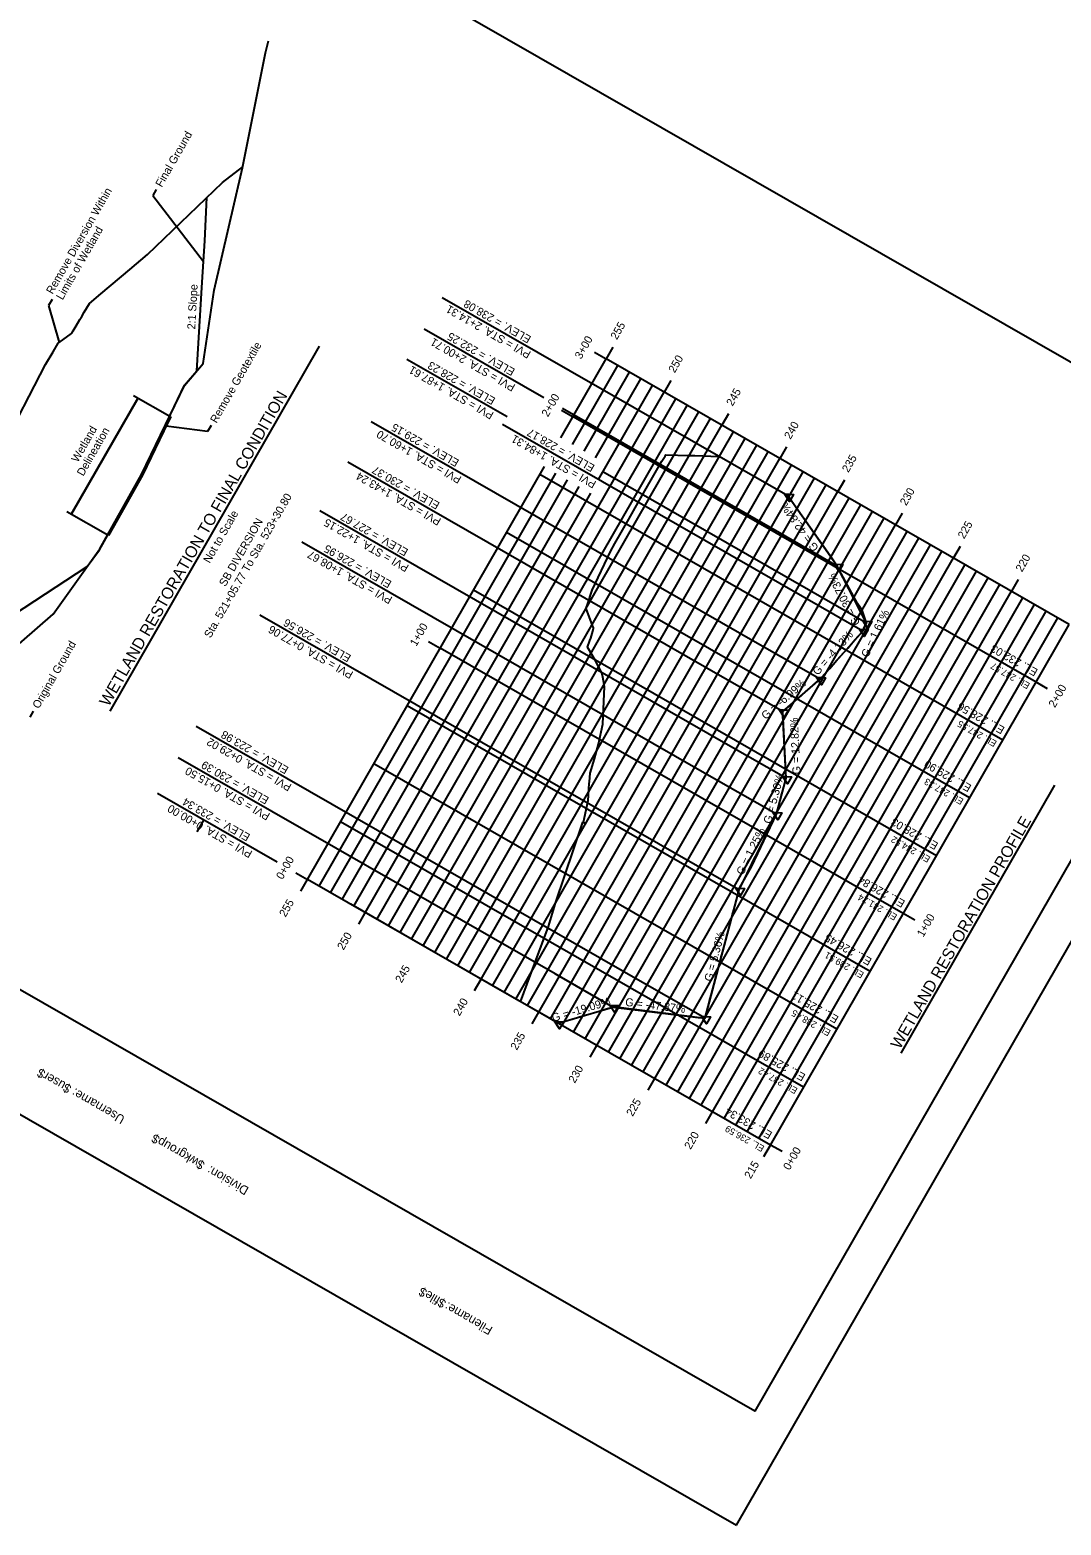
# Model space of a CAD drawing. Extents: x 1160918 to 1162032, y 616868 to 618272.
# Drawn here: x 1161130 to 1161516, y 616868 to 617428 of the extents above; entities that cross this region are included whole.
import ezdxf

# ---------------------------------------------------------------- set-up
doc = ezdxf.new("R2010")
doc.units = 0
for name, color, linetype in [('ANNOTATION', 7, 'Continuous'), ('BORDER', 7, 'Continuous'), ('D_Roadway_Centerline', 7, 'Continuous'), ('D_Roadway_Centerline_CurveData', 7, 'Continuous'), ('D_Roadway_Centerline_Text', 7, 'Continuous'), ('DIMENSIONS', 7, 'Continuous'), ('H_V ANNOTATION', 7, 'Continuous'), ('MAJOR', 7, 'Continuous'), ('MINOR', 7, 'Continuous'), ('PLOT BOUNDARY', 7, 'Continuous'), ('Plot Boundary_1', 7, 'Continuous'), ('S_Roadway_Centerline', 7, 'Continuous')]:
    doc.layers.add(name, color=color, linetype=linetype)

msp = doc.modelspace()

# ---------------------------------------------------------------- linework, layer by layer
at = {"layer": 'ANNOTATION'}
for p, q in [((1161177.15, 617368.59), (1161175.89, 617366.39)), ((1161175.89, 617366.39), (1161194.97, 617341.61)), ((1161138.17, 617327.38), (1161136.91, 617325.18)), ((1161136.91, 617325.18), (1161140.79, 617311.27)), ((1161170.41, 617290.47), (1161145.47, 617246.98)), ((1161145.47, 617246.98), (1161170.41, 617290.47)), ((1161168.69, 617291.45), (1161182.26, 617283.67)), ((1161196.47, 617277.89), (1161180.96, 617279.87)), ((1161197.74, 617280.09), (1161196.47, 617277.89)), ((1161143.75, 617247.97), (1161159.04, 617239.2)), ((1161131.15, 617173.06), (1161129.89, 617170.86))]:
    msp.add_line(p, q, dxfattribs=at)
msp.add_lwpolyline([(1161159.5, 617238.96), (1161164.37, 617247.58), (1161172.16, 617261.48), (1161180.18, 617278.18), (1161182.76, 617283.58)], dxfattribs=at)
at = {"layer": 'BORDER'}
msp.add_lwpolyline([(1160946.07, 617171.9), (1161344.12, 617865.84), (1161799.52, 617604.62), (1161401.47, 616910.68)], close=True, dxfattribs=at)
at = {"layer": 'D_Roadway_Centerline'}
for p, q in [((1161432.4, 617227.46), (1161413.89, 617253.76)), ((1161443.34, 617206.09), (1161432.4, 617227.46)), ((1161441.93, 617203.08), (1161443.34, 617206.09)), ((1161425.95, 617185.03), (1161441.93, 617203.08)), ((1161411.97, 617172.93), (1161425.95, 617185.03)), ((1161413.2, 617147.91), (1161411.97, 617172.93)), ((1161409.59, 617134.44), (1161413.2, 617147.91)), ((1161395.57, 617106.04), (1161409.59, 617134.44)), ((1161382.83, 617057.96), (1161395.57, 617106.04)), ((1161327.79, 617056.08), (1161348.34, 617062.16)), ((1161348.34, 617062.16), (1161382.83, 617057.96))]:
    msp.add_line(p, q, dxfattribs=at)
for points in [[(1161084.35, 617183.4), (1161151.39, 617227.32), (1161155.9, 617233.6), (1161172.14, 617262.58), (1161187.84, 617295.32), (1161192.39, 617300.62), (1161194.47, 617333.83), (1161195.48, 617349.39), (1161196.23, 617365.67), (1161196.56, 617365.98)], [(1161327.79, 617056.08), (1161330.44, 617056.87), (1161333.09, 617057.65), (1161335.75, 617058.44), (1161338.4, 617059.22), (1161341.05, 617060.01), (1161343.7, 617060.79), (1161346.35, 617061.57), (1161348.34, 617062.16), (1161349.61, 617062.01), (1161354.72, 617061.39), (1161359.82, 617060.76), (1161364.93, 617060.14), (1161370.03, 617059.52), (1161375.13, 617058.9), (1161380.24, 617058.28), (1161382.83, 617057.96), (1161383.02, 617058.65), (1161383.02, 617058.65), (1161383.09, 617058.94), (1161383.63, 617060.94), (1161384.16, 617062.95), (1161384.69, 617064.95), (1161385.22, 617066.95), (1161385.75, 617068.95), (1161386.28, 617070.95), (1161386.81, 617072.95), (1161387.34, 617074.96), (1161387.87, 617076.96), (1161388.4, 617078.96), (1161388.93, 617080.96), (1161389.46, 617082.96), (1161389.99, 617084.96), (1161390.52, 617086.96), (1161391.05, 617088.97), (1161391.58, 617090.97), (1161392.11, 617092.97), (1161392.64, 617094.97), (1161393.17, 617096.97), (1161393.7, 617098.97), (1161394.23, 617100.97), (1161394.76, 617102.98), (1161395.29, 617104.98), (1161395.57, 617106.04), (1161395.99, 617106.88), (1161396.03, 617106.95), (1161396.03, 617106.95), (1161396.88, 617108.68), (1161397.76, 617110.48), (1161398.65, 617112.27), (1161399.54, 617114.07), (1161400.43, 617115.87), (1161401.31, 617117.66), (1161402.2, 617119.46), (1161403.09, 617121.26), (1161403.97, 617123.05), (1161404.86, 617124.85), (1161405.75, 617126.65), (1161406.63, 617128.44), (1161407.52, 617130.24), (1161408.41, 617132.04), (1161409.3, 617133.84), (1161409.59, 617134.44), (1161409.95, 617135.77), (1161410.48, 617137.76), (1161411.02, 617139.76), (1161411.55, 617141.76), (1161412.09, 617143.76), (1161412.63, 617145.76), (1161413.16, 617147.76), (1161413.2, 617147.91), (1161413.09, 617150.1), (1161412.98, 617152.47), (1161412.86, 617154.85), (1161412.74, 617157.22), (1161412.63, 617159.59), (1161412.51, 617161.96), (1161412.39, 617164.34), (1161412.28, 617166.71), (1161412.16, 617169.08), (1161412.04, 617171.46), (1161411.97, 617172.93), (1161412.58, 617173.45), (1161414.18, 617174.84), (1161415.78, 617176.23), (1161417.39, 617177.61), (1161418.99, 617179), (1161420.59, 617180.39), (1161422.19, 617181.77), (1161423.79, 617183.16), (1161425.39, 617184.55), (1161425.95, 617185.03), (1161426.83, 617186.03), (1161427.63, 617186.93), (1161428.19, 617187.56), (1161429.54, 617189.09), (1161430.89, 617190.62), (1161432.25, 617192.15), (1161433.6, 617193.68), (1161434.95, 617195.2), (1161436.31, 617196.73), (1161437.66, 617198.26), (1161439.01, 617199.79), (1161440.37, 617201.32), (1161441.72, 617202.85), (1161441.93, 617203.08), (1161442.65, 617204.62), (1161443.34, 617206.09), (1161443.02, 617206.72), (1161441.35, 617209.98), (1161439.68, 617213.25), (1161438.01, 617216.51), (1161436.33, 617219.77), (1161434.66, 617223.04), (1161432.99, 617226.3), (1161432.4, 617227.46), (1161430.64, 617229.96), (1161430.53, 617230.11), (1161430.53, 617230.11), (1161427.92, 617233.82), (1161425.2, 617237.69), (1161422.48, 617241.55), (1161419.76, 617245.42), (1161417.04, 617249.29), (1161414.32, 617253.15), (1161413.89, 617253.76)]]:
    msp.add_lwpolyline(points, dxfattribs=at)
at = {"layer": 'D_Roadway_Centerline_CurveData'}
for p, q in [((1161392.21, 617266.2), (1161284.37, 617328.05)), ((1161322.44, 617290.54), (1161277.6, 617316.25)), ((1161308.65, 617283.35), (1161271.09, 617304.89)), ((1161410.72, 617239.9), (1161329.4, 617286.54)), ((1161404.27, 617197.47), (1161257.69, 617281.54)), ((1161420.24, 617215.52), (1161307, 617280.48)), ((1161390.29, 617185.37), (1161249.01, 617266.4)), ((1161413.89, 617253.76), (1161392.21, 617266.2)), ((1161421.66, 617218.52), (1161344.57, 617262.74)), ((1161391.52, 617160.35), (1161238.52, 617248.11)), ((1161432.4, 617227.46), (1161410.72, 617239.9)), ((1161387.91, 617146.88), (1161231.81, 617236.42)), ((1161441.93, 617203.08), (1161420.24, 617215.52)), ((1161443.34, 617206.09), (1161421.66, 617218.52)), ((1161373.89, 617118.48), (1161216.08, 617209)), ((1161425.95, 617185.03), (1161404.27, 617197.47)), ((1161411.97, 617172.93), (1161390.29, 617185.37)), ((1161361.15, 617070.4), (1161192.17, 617167.32)), ((1161413.2, 617147.91), (1161391.52, 617160.35)), ((1161326.66, 617074.6), (1161185.45, 617155.6)), ((1161409.59, 617134.44), (1161387.91, 617146.88)), ((1161222.57, 617116.43), (1161177.74, 617142.15)), ((1161395.57, 617106.04), (1161373.89, 617118.48)), ((1161306.11, 617068.52), (1161250.07, 617100.66)), ((1161348.34, 617062.16), (1161326.66, 617074.6)), ((1161382.83, 617057.96), (1161361.15, 617070.4)), ((1161327.79, 617056.08), (1161306.11, 617068.52))]:
    msp.add_line(p, q, dxfattribs=at)
for points in [[(1161412.59, 617254.51), (1161415.94, 617254.32), (1161414.45, 617251.71)], [(1161431.1, 617228.2), (1161434.45, 617228.01), (1161432.96, 617225.41)], [(1161442.04, 617206.83), (1161445.39, 617206.64), (1161443.9, 617204.04)], [(1161440.63, 617203.83), (1161443.97, 617203.64), (1161442.48, 617201.04)], [(1161424.65, 617185.78), (1161428, 617185.59), (1161426.51, 617182.98)], [(1161410.67, 617173.67), (1161414.02, 617173.48), (1161412.53, 617170.88)], [(1161411.9, 617148.66), (1161415.25, 617148.47), (1161413.76, 617145.86)], [(1161408.29, 617135.18), (1161411.64, 617134.99), (1161410.15, 617132.39)], [(1161394.27, 617106.78), (1161397.62, 617106.59), (1161396.13, 617103.99)], [(1161347.04, 617062.91), (1161350.39, 617062.72), (1161348.9, 617060.12)], [(1161381.53, 617058.71), (1161384.88, 617058.51), (1161383.39, 617055.91)], [(1161326.49, 617056.83), (1161329.84, 617056.64), (1161328.35, 617054.03)]]:
    msp.add_lwpolyline(points, close=True, dxfattribs=at)
at = {"layer": 'H_V ANNOTATION'}
for p, q in [((1161159.9, 617173.02), (1161238.38, 617309.83)), ((1161456.37, 617044.87), (1161513.96, 617145.27))]:
    msp.add_line(p, q, dxfattribs=at)
at = {"layer": 'MAJOR'}
for p, q in [((1161341.48, 617307.61), (1161345.82, 617305.13)), ((1161348.31, 617309.46), (1161345.82, 617305.13)), ((1161348.31, 617309.46), (1161345.82, 617305.13)), ((1161328.84, 617275.53), (1161345.82, 617305.13)), ((1161519.31, 617205.61), (1161345.82, 617305.13)), ((1161369.99, 617297.02), (1161367.51, 617292.69)), ((1161255.56, 617097.52), (1161367.51, 617292.69)), ((1161329.05, 617285.93), (1161333.38, 617283.44)), ((1161506.87, 617183.93), (1161333.38, 617283.44)), ((1161391.68, 617284.58), (1161389.19, 617280.25)), ((1161277.24, 617085.08), (1161389.19, 617280.25)), ((1161413.36, 617272.14), (1161410.88, 617267.81)), ((1161298.93, 617072.64), (1161410.88, 617267.81)), ((1161233.87, 617109.95), (1161322.67, 617264.76)), ((1161320.61, 617060.2), (1161432.56, 617255.37)), ((1161435.05, 617259.71), (1161432.56, 617255.37)), ((1161456.74, 617247.27), (1161454.25, 617242.93)), ((1161342.3, 617047.76), (1161454.25, 617242.93)), ((1161478.42, 617234.83), (1161475.93, 617230.49)), ((1161363.98, 617035.32), (1161475.93, 617230.49)), ((1161500.11, 617222.39), (1161497.62, 617218.05)), ((1161385.67, 617022.88), (1161497.62, 617218.05)), ((1161407.36, 617010.44), (1161519.31, 617205.61)), ((1161279.29, 617199.18), (1161283.63, 617196.7)), ((1161457.11, 617097.19), (1161283.63, 617196.7)), ((1161511.2, 617181.44), (1161506.87, 617183.93)), ((1161192.55, 617127.89), (1161195.03, 617132.23)), ((1161229.53, 617112.44), (1161233.87, 617109.95)), ((1161231.38, 617105.62), (1161233.87, 617109.95)), ((1161231.38, 617105.62), (1161233.87, 617109.95)), ((1161407.36, 617010.44), (1161233.87, 617109.95)), ((1161253.07, 617093.18), (1161255.56, 617097.52)), ((1161461.45, 617094.7), (1161457.11, 617097.19)), ((1161296.44, 617068.3), (1161298.93, 617072.64)), ((1161318.12, 617055.86), (1161320.61, 617060.2)), ((1161339.81, 617043.42), (1161342.3, 617047.76)), ((1161361.5, 617030.98), (1161363.98, 617035.32)), ((1161383.18, 617018.54), (1161385.67, 617022.88)), ((1161404.87, 617006.11), (1161407.36, 617010.44)), ((1161411.69, 617007.96), (1161407.36, 617010.44))]:
    msp.add_line(p, q, dxfattribs=at)
at = {"layer": 'MINOR'}
for p, q in [((1161333.18, 617273.04), (1161350.16, 617302.64)), ((1161337.52, 617270.55), (1161354.49, 617300.15)), ((1161519.31, 617205.61), (1161345.82, 617305.13)), ((1161341.85, 617268.06), (1161358.83, 617297.66)), ((1161342.92, 617259.88), (1161363.17, 617295.18)), ((1161259.89, 617095.03), (1161371.84, 617290.2)), ((1161264.23, 617092.54), (1161376.18, 617287.71)), ((1161268.57, 617090.05), (1161380.52, 617285.22)), ((1161272.9, 617087.56), (1161384.85, 617282.74)), ((1161281.58, 617082.59), (1161393.53, 617277.76)), ((1161285.92, 617080.1), (1161397.87, 617275.27)), ((1161290.25, 617077.61), (1161402.2, 617272.78)), ((1161294.59, 617075.13), (1161406.54, 617270.3)), ((1161238.21, 617107.47), (1161327, 617262.27)), ((1161303.26, 617070.15), (1161415.21, 617265.32)), ((1161307.6, 617067.66), (1161419.55, 617262.83)), ((1161311.94, 617065.17), (1161423.89, 617260.35)), ((1161494.43, 617162.24), (1161320.94, 617261.75)), ((1161242.54, 617104.98), (1161331.34, 617259.78)), ((1161246.88, 617102.49), (1161335.68, 617257.29)), ((1161251.22, 617100), (1161340.01, 617254.81)), ((1161316.28, 617062.69), (1161428.23, 617257.86)), ((1161324.95, 617057.71), (1161436.9, 617252.88)), ((1161329.29, 617055.22), (1161441.24, 617250.39)), ((1161333.62, 617052.74), (1161445.57, 617247.91)), ((1161337.96, 617050.25), (1161449.91, 617245.42)), ((1161481.99, 617140.56), (1161308.5, 617240.07)), ((1161346.64, 617045.27), (1161458.59, 617240.44)), ((1161350.97, 617042.78), (1161462.92, 617237.96)), ((1161355.31, 617040.3), (1161467.26, 617235.47)), ((1161359.65, 617037.81), (1161471.6, 617232.98)), ((1161368.32, 617032.83), (1161480.27, 617228)), ((1161372.66, 617030.34), (1161484.61, 617225.52)), ((1161377, 617027.86), (1161488.95, 617223.03)), ((1161469.55, 617118.87), (1161296.06, 617218.38)), ((1161381.33, 617025.37), (1161493.28, 617220.54)), ((1161390.01, 617020.39), (1161501.96, 617215.57)), ((1161394.34, 617017.91), (1161506.29, 617213.08)), ((1161398.68, 617015.42), (1161510.63, 617210.59)), ((1161403.02, 617012.93), (1161514.97, 617208.1)), ((1161444.67, 617075.5), (1161271.19, 617175.01)), ((1161432.23, 617053.81), (1161258.75, 617153.33)), ((1161419.79, 617032.13), (1161246.31, 617131.64))]:
    msp.add_line(p, q, dxfattribs=at)
at = {"layer": 'PLOT BOUNDARY'}
msp.add_lwpolyline([(1161394.6, 616867.96), (1161817.53, 617605.28), (1161340.44, 617878.94), (1160917.52, 617141.62)], close=True, dxfattribs=at)
at = {"layer": 'Plot Boundary_1'}
msp.add_lwpolyline([(1161145.09, 617518.87), (1161319.24, 617822.47), (1161774.64, 617561.25), (1161600.49, 617257.65)], close=True, dxfattribs=at)
at = {"layer": 'S_Roadway_Centerline'}
for points in [[(1161051.23, 617132.33), (1161059.14, 617140.2), (1161138.59, 617209.45), (1161156.14, 617233.94), (1161171.73, 617261.73), (1161187.76, 617295.14), (1161194.77, 617303.43), (1161198.86, 617330.93), (1161209.57, 617376.77), (1161218.15, 617419.8), (1161219.3, 617424.37)], [(1161119.38, 617271.24), (1161135.76, 617303.05), (1161138.55, 617307.82), (1161140.41, 617310.99), (1161142.18, 617312.28), (1161145.48, 617314.69), (1161145.54, 617314.79), (1161145.56, 617314.82), (1161146.05, 617315.63), (1161147.21, 617317.57), (1161148.59, 617319.86), (1161149.29, 617321.02), (1161150.26, 617322.64), (1161152.16, 617325.9), (1161156.41, 617329.47), (1161167.32, 617338.64), (1161173.96, 617344.22), (1161202.04, 617371.27), (1161209.66, 617377.17)], [(1161313.7, 617064.16), (1161319.06, 617078.59), (1161324.2, 617092.39), (1161326.77, 617101.07), (1161337.02, 617131.45), (1161337.63, 617131.22), (1161337.32, 617131.42), (1161339.04, 617139.64), (1161339.16, 617141.46), (1161339.32, 617143.79), (1161339.48, 617146.03), (1161339.52, 617146.61), (1161339.74, 617149.77), (1161341.45, 617155.2), (1161342.96, 617160.75), (1161344.53, 617168.19), (1161345.14, 617182.26), (1161345.04, 617182.85), (1161345.01, 617183.03), (1161344.51, 617185.84), (1161344.22, 617187.48), (1161341.62, 617192.13), (1161339.19, 617196.49), (1161338.85, 617197.09), (1161339.71, 617199.58), (1161340, 617200.41), (1161340.76, 617203.03), (1161341.09, 617204.15), (1161341.08, 617204.25), (1161341.07, 617204.29), (1161340.73, 617205.16), (1161338.25, 617211.54), (1161338.31, 617211.7), (1161338.75, 617212.99), (1161340.53, 617218.38), (1161347.41, 617232.95), (1161349.07, 617235.86), (1161354.27, 617245.01), (1161357.82, 617251.23), (1161366.15, 617265.91), (1161366.63, 617266.77), (1161367.89, 617268.7), (1161368.21, 617269.21), (1161377.08, 617268.93), (1161377.61, 617268.91), (1161378.98, 617268.87), (1161388.05, 617268.58)], [(1161327.79, 617056.08), (1161348.34, 617062.16), (1161348.41, 617062.37), (1161348.42, 617062.4), (1161382.83, 617057.96), (1161382.84, 617057.97), (1161382.98, 617058.67), (1161395.57, 617106.04), (1161395.94, 617107.01), (1161400.22, 617114.75), (1161409.59, 617134.44), (1161413.2, 617147.91), (1161411.97, 617172.93), (1161425.95, 617185.03), (1161427.6, 617186.95), (1161441.93, 617203.08), (1161443.34, 617206.09), (1161441.75, 617210.92), (1161440.01, 617213.45), (1161432.4, 617227.46), (1161430.66, 617230.04), (1161413.89, 617253.76)]]:
    msp.add_lwpolyline(points, dxfattribs=at)

# ---------------------------------------------------------------- texts
at = {"layer": 'ANNOTATION'}
for s, height, rotation, p in [('Final Ground', 3, 60.1613, (1161179.3, 617369.23)), ('Remove Diversion Within', 3, 60.1613, (1161138.36, 617329.14)), ('Limits of Wetland', 3, 60.1613, (1161142.12, 617326.98)), ('Remove Geotextile', 3, 60.1613, (1161199.81, 617280.78)), ('WETLAND RESTORATION TO FINAL CONDITION', 4.3749, 60.1613, (1161159.42, 617174.51)), ('Wetland ', 3, 60.1613, (1161147.84, 617266.11)), ('Delineation', 3, 60.1613, (1161149.87, 617260.94)), ('Original Ground', 3, 60.1613, (1161133.22, 617173.75)), ('EL. 247.57', 2.5, 150.1613, (1161504.82, 617183.37)), ('EL. 247.55', 2.5, 150.1613, (1161492.38, 617161.69)), ('EL. 247.33', 2.5, 150.1613, (1161479.94, 617140)), ('EL. 244.52', 2.5, 150.1613, (1161467.5, 617118.32)), ('EL. 241.24', 2.5, 150.1613, (1161455.06, 617096.63)), ('EL. 239.51', 2.5, 150.1613, (1161442.62, 617074.94)), ('EL. 238.45', 2.5, 150.1613, (1161430.19, 617053.26)), ('EL. 237.42', 2.5, 150.1613, (1161417.75, 617031.57)), ('EL. 236.59', 2.5, 150.1613, (1161405.31, 617009.89))]:
    msp.add_text(s, height=height, rotation=rotation, dxfattribs=at).set_placement(p)
at = {"layer": 'BORDER'}
for s, p in [('$user$', (1161145.72, 617032.5)), ('Username:', (1161165.78, 617021)), ('$wkgroup$', (1161195.69, 617003.84)), ('Division:', (1161212.19, 616994.37)), ('$file$', (1161286.1, 616951.98)), ('Filename:', (1161303.56, 616941.96))]:
    msp.add_text(s, height=3.348, rotation=150.1613, dxfattribs=at).set_placement(p)
at = {"layer": 'D_Roadway_Centerline_CurveData'}
for s, rotation, p in [('2:1 Slope', 86.7818, (1161191.8, 617316.12)), ('PVI = STA. 2+14.31', 150.1613, (1161317.88, 617307.68)), ('ELEV. = 238.08', 150.1613, (1161317.97, 617313.39)), ('PVI = STA. 2+00.71', 150.1613, (1161312.04, 617295.34)), ('ELEV. = 232.25', 150.1613, (1161311.9, 617301.19)), ('PVI = STA. 1+87.61', 150.1613, (1161303.95, 617284.89)), ('ELEV. = 228.23', 150.1613, (1161304.55, 617290.31)), ('PVI = STA. 1+60.70', 150.1613, (1161291.86, 617260.79)), ('ELEV. = 229.15', 150.1613, (1161290.95, 617267.08)), ('ELEV. = 228.17', 150.1613, (1161341.77, 617265.15)), ('PVI = STA. 1+84.31', 150.1613, (1161342.36, 617259.04)), ('PVI = STA. 1+43.24', 150.1613, (1161284.21, 617245.06)), ('ELEV. = 230.37', 150.1613, (1161283.71, 617251.11)), ('G = 42.84%', 125.1357, (1161425.6, 617234.22)), ('PVI = STA. 1+22.15', 150.1613, (1161272.14, 617227.67)), ('ELEV. = 227.67', 150.1613, (1161271.89, 617233.58)), ('PVI = STA. 1+08.67', 150.1613, (1161265.97, 617215.67)), ('ELEV. = 226.95', 150.1613, (1161265.67, 617221.61)), ('G = 30.73%', 117.1049, (1161441.09, 617206.09)), ('G = 1.61%', 64.768, (1161443.89, 617192.95)), ('PVI = STA. 0+77.06', 150.1613, (1161251.31, 617187.63)), ('ELEV. = 226.56', 150.1613, (1161250.49, 617193.87)), ('G = -4.13%', 48.4966, (1161425.06, 617186.26)), ('G = -6.99%', 40.8852, (1161405.53, 617169.72)), ('ELEV. = 223.98', 150.1613, (1161227.09, 617151.91)), ('G = 12.82%', 92.8158, (1161418.65, 617149.45)), ('PVI = STA. 0+29.02', 150.1613, (1161228.22, 617145.49)), ('ELEV. = 230.39', 150.1613, (1161219.72, 617140.56)), ('PVI = STA. 0+15.50', 150.1613, (1161220.13, 617134.56)), ('G = 5.30%', 75.0035, (1161407.54, 617130.66)), ('PVI = STA. 0+00.00', 150.1613, (1161213.53, 617120.47)), ('ELEV. = 233.34', 150.1613, (1161212.68, 617126.72)), ('G = 1.25%', 63.7276, (1161397.09, 617111.38)), ('G = 5.36%', 75.1589, (1161385.39, 617071.53)), ('G = -19.09%', 16.4903, (1161325.96, 617056.59)), ('G = -47.37%', 353.0505, (1161352.81, 617062.63))]:
    msp.add_text(s, height=3, rotation=rotation, dxfattribs=at).set_placement(p)
at = {"layer": 'D_Roadway_Centerline_Text'}
for s, p in [('EL. 232.03', (1161507.81, 617188.58)), ('EL. 228.56', (1161495.37, 617166.89)), ('EL. 229.90', (1161482.93, 617145.21)), ('EL. 228.03', (1161470.49, 617123.52)), ('EL. 226.84', (1161458.05, 617101.84)), ('EL. 226.45', (1161445.61, 617080.15)), ('EL. 225.11', (1161433.17, 617058.46)), ('EL. 225.89', (1161420.73, 617036.78)), ('EL. 233.34', (1161408.29, 617015.09))]:
    msp.add_text(s, height=3, rotation=150.1613, dxfattribs=at).set_placement(p)
at = {"layer": 'DIMENSIONS'}
for s, p in [('Sta. 521+05.77 To Sta. 523+30.80', (1161197.54, 617200.22)), ('Not to Scale', (1161197.23, 617228.31)), ('SB DIVERSION', (1161203.14, 617219.54))]:
    msp.add_text(s, height=3, rotation=60.1613, dxfattribs=at).set_placement(p)
at = {"layer": 'H_V ANNOTATION'}
for s, height, p in [('255', 3, (1161349.8, 617312.06)), ('255', 3, (1161349.8, 617312.06)), ('3+00', 3, (1161336.41, 617304.79)), ('250', 3, (1161371.49, 617299.62)), ('245', 3, (1161393.17, 617287.19)), ('2+00', 3, (1161323.98, 617283.13)), ('240', 3, (1161414.86, 617274.75)), ('235', 3, (1161436.54, 617262.31)), ('230', 3, (1161458.23, 617249.87)), ('225', 3, (1161479.91, 617237.43)), ('220', 3, (1161501.6, 617224.99)), ('1+00', 3, (1161274.65, 617197.13)), ('2+00', 3, (1161513.94, 617174.16)), ('WETLAND RESTORATION PROFILE', 4.3749, (1161455.89, 617046.06)), ('0+00', 3, (1161224.52, 617109.73)), ('255', 3, (1161225.67, 617095.66)), ('255', 3, (1161225.67, 617095.66)), ('1+00', 3, (1161464.61, 617088.16)), ('250', 3, (1161247.39, 617083.29)), ('245', 3, (1161269.15, 617070.96)), ('240', 3, (1161290.87, 617058.59)), ('235', 3, (1161312.33, 617045.76)), ('230', 3, (1161334.06, 617033.39)), ('225', 3, (1161355.73, 617020.93)), ('220', 3, (1161377.45, 617008.56)), ('0+00', 3, (1161414.49, 617000.77)), ('215', 3, (1161399.95, 616997.54))]:
    msp.add_text(s, height=height, rotation=60.1613, dxfattribs=at).set_placement(p)

doc.saveas('drawing.dxf')
